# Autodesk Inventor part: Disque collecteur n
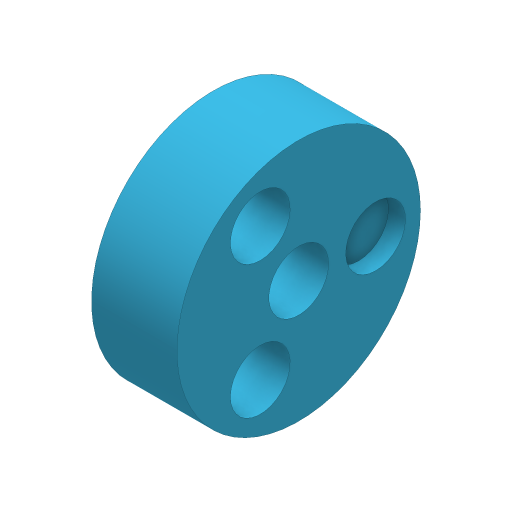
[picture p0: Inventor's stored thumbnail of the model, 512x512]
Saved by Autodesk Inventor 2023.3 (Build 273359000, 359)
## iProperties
Created: 2017-03
Part Number: Disque collecteur n
Material: Générique
Document SubType Name: Modeling
Designer: thierry.jost
Density: 1 g/cm^3
Appearance: Turquoise
Author: thierry.jost
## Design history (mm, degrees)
sketch "Sketch1"
  geometry: C1 r 14.25 at (0, 0); 1 further point
  constraints: 1 centre point, 1 coincident
  dimensions: "d0" = 28.5 diameter of C1
extrude "Extrusion1" new body sketch "Sketch1" distance "d1" = 10; taper "d2" = 0 deg
sketch "Sketch2"
  geometry: 2 further points
  dimensions: "d3" = 0 horizontal distance of point (0, 0) point (0, 9); "d4" = 9 distance of point (0, 9) point (0, 0)
hole "Hole1" sketch "Sketch2" at (0, 9) diameter "d5" = 7; stored, may be unused: countersink angle "d9" = 90 deg, drill point angle "d11" = 0 deg; dims "d6" = 6, "d7" = 7, "d8" = 2, "d10" = 2
hole "Hole2" diameter "d14" = 7; stored, may be unused: countersink angle "d18" = 90 deg, drill point angle "d20" = 118 deg; dims "d12" = 10, "d13" = 10, "d15" = 6, "d16" = 7, "d17" = 2, "d19" = 8
sketch "Sketch3"
  geometry: L1 (0, 0)-(-7.794, -4.5); L2 (0, 0)-(0, -16.389)
  constraints: 4 end point, 1 vertical
  dimensions: "d21" = 9 distance of L1.start L1.end; "d22" = 60 deg angle of L1 L2
hole "Hole3" sketch "Sketch3" at (-7.794, -4.5) diameter "d23" = 7; stored, may be unused: countersink angle "d27" = 90 deg, drill point angle "d29" = 118 deg; dims "d24" = 6, "d25" = 7, "d26" = 2, "d28" = 8
pattern_circular "Circular Pattern1" dims angle "d31" = 120 deg
body "Solid1"
